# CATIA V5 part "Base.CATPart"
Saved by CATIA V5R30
Part number: Part1
Bounding box of the stored display mesh (mm): x -50 to 50, y -25 to 25, z 0 to 50
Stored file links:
  D:\PROJECTS\CATIA V56R 2020\Resources\Parts File\c12_catia_v5_6r2020_prt\c12_catia_v5-6r2020 figr_12-12\Base.CATPart
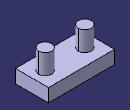
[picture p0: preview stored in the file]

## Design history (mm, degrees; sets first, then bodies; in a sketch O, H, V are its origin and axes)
Body1 (main body)
  Sketch1 on xy-plane, origin (0, 0, 0), H (1, 0, 0), V (0, 1, 0)
    line L1 (50, 25) -> (50, -25)
    line L2 (50, -25) -> (-50, -25)
    line L3 (-50, -25) -> (-50, 25)
    line L4 (-50, 25) -> (50, 25)
    circle A1 centre (-30, 0) radius 10
    point P5 (-30, 0)
    circle A2 centre (30, 0) radius 10
    length L2 = 100
    length L1 = 50
    radius A1 = 10
    distance P5 V = 30
    vertical: L1 V, L3 V
    horizontal: L2 H, L4 H
    equidistance: L1 L3 O, L2 L4 O
    coincidence: P5 H
    symmetry: A1 A2 V
  MultiPad1: profile Sketch1, domains (length 20; length 50; length 50)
